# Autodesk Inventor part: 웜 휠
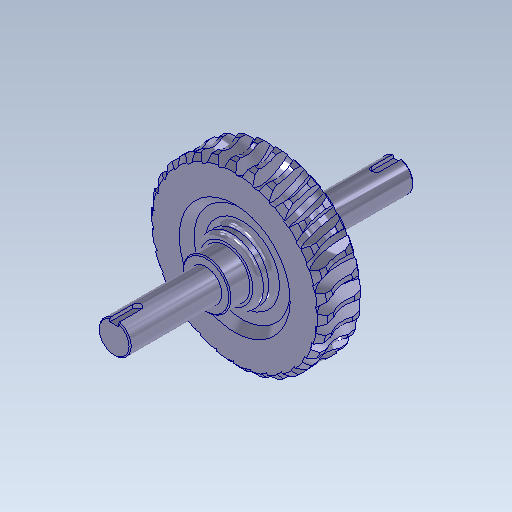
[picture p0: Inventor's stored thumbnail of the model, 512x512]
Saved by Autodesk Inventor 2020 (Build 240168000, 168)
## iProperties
CustomPartVersion: 1
Created: 2013-01
Part Number: 웜 휠
Material: 일반
Document SubType Name: Modeling
Designer: 한국산업디자인학원[gmhk.co.kr]
Categories: <?xml version="1.0" encoding="UTF-16"?> <MemberInstance><Categories><FamilyTemplate><FamilyTemplateParameter ValueType="xs:double" Id="1" ObjectReferenceKey="da
Density: 1 g/cm^3
Mass: 888.112 g
Surface Area: 1041.74 cm^2
Volume: 888.112 cm^3
Appearance: _시험-파란색 크롬
Author: 한국산업디자인학원[gmhk.co.kr]
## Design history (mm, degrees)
node "톱니 평면"
sketch "기본 본체 스케치"
  geometry: L1 (0, -14)-(0, 14) reference; L2 (0, 20)-(77.639, 20); L3 (77.639, 20)-(82.5, 15.652); L4 (-10, 0)-(60, 0) reference; L5 (82.5, 15.652)-(82.5, -15.652); L6 (0, -20)-(77.639, -20); L7 (0, 20)-(0, -20); L8 (77.639, -20)-(82.5, -15.652); C1 r 20 at (100, 0)
  constraints: 14 end point, 3 symmetric about line, 2 perpendicular, 2 point on line, 1 centre point, 1 collinear
  dimensions: "d50" = 41.8103 deg angle of L3 L2 (= da_fi); "d87" = 165 diameter of L5 L1 (= da_dae); "d89" = 40 diameter of C1 (= 2 x da_aw - da_da); "d92" = 40 distance of L2.start L6.start (= da_b); "d93" = 100 distance from line of C1.centre L7 (= da_aw)
revolve "기본 본체" stored, may be unused: angle "d35" = 90 deg
revolve "기본 본체2" stored, may be unused: angle "d90" = 90 deg
feature "피치 지름" dims "d78" = 40 (= da_b), "d79" = 0
workplane "Work Plane13"
sketch "톱니 스케치"
  geometry: L1 (10, 5.301)-(10, -5.301) reference; L2 (-32.842, 0)-(-12.948, 0) reference; L3 (-90, 6.896)-(-90, -6.896); L4 (-90, -6.896)-(-71, -6.896); L5 (-71, -6.896)-(-59, -2.529); L6 (-59, -2.529)-(-59, 0); L7 (-59, 2.529)-(-71, 6.896); L8 (-71, 6.896)-(-90, 6.896); L9 (-59, 2.529)-(-59, 0); L10 (-65, 0)-(-65, -4.712)
  constraints: 16 end point, 4 perpendicular, 3 equal length, 2 point on line, 1 midpoint, 1 parallel, 1 vertical
  dimensions: "d38" = 100 distance between parallel lines of L1 L3 (= da_aw); "d39" = 20 deg angle of L7 L8 (= da_alfat); "d40" = 19 distance of L7.end L3.start (= 0.5 x da_df1); "d41" = 25 distance between parallel lines of L3 L10 (= 0.5 x da_d1); "d42" = 4.71239 distance of L10.start L10.end (= 0.3 x da_px)
revolve "톱니" sketch "톱니 스케치" stored, may be unused: angle "d43" = 90 deg
workplane "Work Plane14"
workplane "Work Plane15"
sketch "스케치9"
  geometry: L1 (-74.283, 20)-(-74.054, 20) reference; L2 (-74.054, 20)-(-74.261, 20) reference; L3 (-74.261, 20)-(-75.727, 20) reference; L4 (-77.355, 20)-(-75.727, 20) reference; L5 (-77.355, 20)-(-77.106, 20) reference; L6 (-77.106, 20)-(-76.222, 20) reference; L7 (-76.222, 20)-(-77.633, 20) reference; L8 (-77.045, 20)-(-77.633, 20) reference; L9 (-77.045, 20)-(-76.789, 20) reference; L10 (-76.789, 20)-(-74.852, 20) reference; L11 (-74.852, 20)-(-76.145, 20) reference; L12 (-73.369, 20)-(-76.145, 20) reference; L13 (-73.369, 20)-(-73.116, 20) reference; L14 (-73.116, 20)-(-70.211, 20) reference; L15 (-70.211, 20)-(-71.33, 20) reference; L16 (-66.486, 20)-(-71.33, 20) reference; L17 (-66.486, 20)-(-66.247, 20) reference; L18 (-66.247, 20)-(-62.501, 20) reference; L19 (-62.501, 20)-(-63.397, 20) reference; L20 (-56.697, 20)-(-63.397, 20) reference; L21 (-56.697, 20)-(-56.483, 20) reference; L22 (-56.483, 20)-(-52.059, 20) reference; L23 (-52.059, 20)-(-52.693, 20) reference; L24 (-44.431, 20)-(-52.693, 20) reference; L25 (-44.431, 20)-(-44.25, 20) reference; L26 (-44.25, 20)-(-39.342, 20) reference; L27 (-39.342, 20)-(-39.687, 20) reference; L28 (-30.222, 20)-(-39.687, 20) reference; L29 (-30.222, 20)-(-30.084, 20) reference; L30 (-30.084, 20)-(-24.906, 20) reference; L31 (-24.906, 20)-(-24.945, 20) reference; L32 (-14.693, 20)-(-24.945, 20) reference; L33 (-14.693, 20)-(-14.602, 20) reference; L34 (-14.602, 20)-(-9.381, 20) reference; L35 (-9.381, 20)-(-9.114, 20) reference; L36 (1.479, 20)-(-9.114, 20) reference; L37 (1.479, 20)-(1.517, 20) reference; L38 (1.517, 20)-(6.554, 20) reference; L39 (6.554, 20)-(7.116, 20) reference; L40 (17.586, 20)-(7.116, 20) reference; L41 (17.586, 20)-(17.571, 20) reference; L42 (17.571, 20)-(22.202, 20) reference; L43 (22.202, 20)-(23.034, 20) reference; L44 (32.924, 20)-(23.034, 20) reference; L45 (32.924, 20)-(32.856, 20) reference; L46 (32.856, 20)-(36.88, 20) reference; L47 (36.88, 20)-(37.946, 20) reference; L48 (46.823, 20)-(37.946, 20) reference; L49 (46.823, 20)-(46.705, 20) reference; L50 (46.705, 20)-(49.946, 20) reference; L51 (49.946, 20)-(51.2, 20) reference; L52 (58.676, 20)-(51.2, 20) reference; L53 (58.676, 20)-(58.514, 20) reference; L54 (58.514, 20)-(60.83, 20) reference; L55 (60.83, 20)-(62.216, 20) reference; L56 (67.965, 20)-(62.216, 20) reference; L57 (67.965, 20)-(67.764, 20) reference; L58 (67.764, 20)-(69.055, 20) reference; L59 (69.055, 20)-(70.512, 20) reference; L60 (74.283, 20)-(70.512, 20) reference; L61 (74.283, 20)-(74.054, 20) reference; L62 (74.054, 20)-(74.261, 20) reference; L63 (74.261, 20)-(75.727, 20) reference; L64 (77.355, 20)-(75.727, 20) reference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
  constraints: 8 end point, 3 point on line, 2 perpendicular, 1 parallel
  dimensions: "d94" = 90 diameter of L122.end L121; "d95" = 135 deg angle of L123 L122; "d96" = 13 distance from line of L121.start L122
revolve "회전6" sketch "스케치9" stored, may be unused: angle "d97" = 90 deg
sketch "스케치10"
  geometry: L1 (45, 13)-(-45, 13) reference; L2 (0, 13)-(0, 133); L3 (0, 133)-(-15, 133); L4 (-15, 133)-(-15, 47); L5 (-15, 47)-(-22.5, 47); L6 (-22.5, 47)-(-22.5, 28); L7 (-22.5, 28)-(-30, 28); L8 (-30, 28)-(-30, 13); L9 (30, 47)-(-30, 47) reference; 1 further point
  constraints: 14 end point, 4 parallel, 3 perpendicular, 1 collinear, 1 midpoint, 1 point on line
  dimensions: "d99" = 30 diameter of L4 L2; "d100" = 45 diameter of L6 L2; "d101" = 60 diameter of L8 L2; "d102" = 15 distance between parallel lines of L7 L1; "d103" = 120 distance of L2.start L2.end
revolve "회전7" sketch "스케치10" stored, may be unused: angle "d104" = 90 deg
fillet "모깎기1" dims "d105" = 5
chamfer "모따기1" distance "d106" = 1; stored, may be unused: second distance "d107" = 2, angle "d108" = 45 deg
node "작업 평면16"
sketch "스케치11"
  geometry: L1 (-14, 43)-(14, 43) reference; L2 (4, 43)-(4, 22); L3 (-4, 22)-(-4, 43); A1 r 4 centre (0, 22) between (-4, 22) and (4, 22); 2 further points
  constraints: 4 end point, 2 perpendicular, 2 point on circle, 2 point on line, 2 tangent, 1 centre point, 1 midpoint, 1 vertical alignment
  dimensions: "d109" = 8 distance between parallel lines of L2 L3; "d110" = 25 dimension on A1 L1
extrude "돌출1" cut sketch "스케치11" distance "d111" = 4; taper "d112" = 0 deg
body "Solid1"
pattern_circular "톱니 패턴" dims angle "d46" = 360 deg
mirror "대칭1"
sketch "Sketch8"
  geometry: C1 r 77.639 at (0, 0) reference; C2 r 75 at (0, 0)
  constraints: 1 centre point, 1 coincident
  dimensions: "d77" = 150 diameter of C2 (= da_dw)
body "Srf1"
node "투영된 루프1"
node "참조1"
other parameters: "da_aw" = 100 [user parameter; used in 5 equation terms], "da_fi" = 41.8103 deg [user parameter; used in 1 equation term], "da_b" = 40 [user parameter; used in 2 equation terms], "da_df" = 138 [user parameter], "da_beta" = 1.97396 [user parameter; used in 1 equation term], "da_alfat" = 20 deg [user parameter; used in 1 equation term], "da_df1" = 38 [user parameter; used in 1 equation term], "da_px" = 90 deg [user parameter; used in 1 equation term], "d37" = -1.97396 (computed from da_rightdir, da_beta), "d69" = 0, "d73" = 0, "d75" = 6 deg (computed from da_z), "da_dw" = 150 [user parameter; used in 1 equation term], "da_rightdir" = 0 [user parameter; used in 1 equation term], "d80" = 0, "d81" = 0, "d82" = 0, "d83" = 6 deg (computed from da_z), "d84" = 0, "d85" = 180 deg, "da_dae" = 165 [user parameter; used in 1 equation term]
